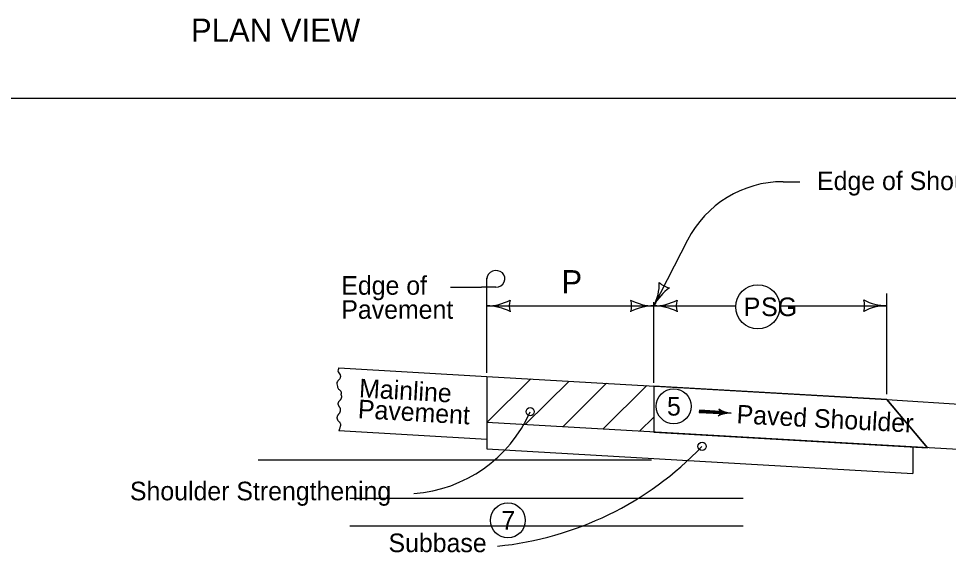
# Model space of a CAD drawing. Extents: x 6410 to 81668, y 3928 to 11667.
# Drawn here: x 7264 to 8064, y 8966 to 9425 of the extents above; entities that cross this region are included whole.
import ezdxf

# ---------------------------------------------------------------- set-up
doc = ezdxf.new("R2010")
doc.units = 0
for name, color, linetype in [('dsnCellElements', 7, 'Continuous'), ('dsnStdBlockModified', 7, 'Continuous'), ('dsnStdLabel', 7, 'Continuous'), ('dsnStdSection', 7, 'Continuous'), ('Level 11', 7, 'Continuous'), ('Level 14', 7, 'Continuous'), ('Level 3', 7, 'Continuous'), ('Level 7', 7, 'Continuous')]:
    doc.layers.add(name, color=color, linetype=linetype)

msp = doc.modelspace()

# ---------------------------------------------------------------- linework, layer by layer
at = {"layer": 'dsnStdBlockModified'}
for p, q in [((7539.49, 9124.58), (7666.95, 9117.17)), ((7666.95, 9117.17), (7666.95, 9063.16)), ((7666.95, 9117.17), (8011.25, 9097.15)), ((7810.72, 9108.8), (7810.72, 9069)), ((8010.79, 9097.34), (8010.79, 9097.34)), ((8011.25, 9097.23), (8146.01, 9088.85)), ((8011.25, 9097.15), (8046.29, 9055.7)), ((8243.06, 9044.35), (7666.95, 9077.58)), ((7539.52, 9070.57), (7666.95, 9063.16)), ((8033.48, 9070.85), (8033.48, 9070.85)), ((7666.95, 9063.16), (7666.95, 9054.74)), ((7666.95, 9054.74), (8033.48, 9033.6)), ((8033.48, 9056.43), (8033.48, 9033.6)), ((7470.23, 9045.23), (7808.74, 9045.23)), ((7548.9, 9012.25), (7887.4, 9012.25)), ((7548.9, 8988.58), (7887.4, 8988.58))]:
    msp.add_line(p, q, dxfattribs=at)
for points in [[(7539.49, 9124.58), (7538.99, 9120.98), (7540.03, 9119.47), (7540.89, 9117.18), (7540.29, 9115.12), (7538.38, 9112.74), (7537.86, 9110.84), (7538.38, 9108.54), (7539.25, 9106.17), (7540.29, 9105.45), (7541.67, 9102.92), (7541.66, 9102.08)], [(7539.7, 9084.97), (7539.91, 9085.22), (7540.11, 9085.48), (7540.46, 9086.04), (7540.74, 9086.63), (7540.86, 9086.93), (7540.96, 9087.25), (7541.09, 9087.87), (7541.14, 9088.49), (7541.1, 9089.08), (7541.04, 9089.35), (7541, 9089.49), (7540.95, 9089.62), (7540.74, 9090), (7540.46, 9090.36), (7540.16, 9090.73), (7539.91, 9091.12), (7539.77, 9091.41), (7539.63, 9091.69), (7539.37, 9092.26), (7539.17, 9092.83), (7539.1, 9093.12), (7539.04, 9093.42), (7539.03, 9093.55), (7539.03, 9093.67), (7539.18, 9094.45), (7539.39, 9094.97), (7539.65, 9095.48), (7540.1, 9096.12), (7540.61, 9096.66), (7541.13, 9097.21), (7541.36, 9097.51), (7541.56, 9097.86), (7541.77, 9098.33), (7541.92, 9098.8), (7542.02, 9099.28), (7542.06, 9099.52), (7542.07, 9099.64), (7542.08, 9099.76), (7542.03, 9100.26), (7541.88, 9100.78), (7541.83, 9100.91), (7541.77, 9101.03), (7541.73, 9101.16), (7541.7, 9101.29), (7541.66, 9102.08)], [(7539.7, 9084.97), (7539.49, 9084.73), (7539.24, 9084.5), (7539, 9084.26), (7538.82, 9083.99), (7538.68, 9083.7), (7538.54, 9083.42), (7538.28, 9082.85), (7538.17, 9082.56), (7538.08, 9082.28), (7538, 9081.98), (7537.98, 9081.84), (7537.96, 9081.69), (7537.97, 9081.17), (7538.1, 9080.66), (7538.3, 9080.14), (7538.56, 9079.63), (7539.01, 9078.99), (7539.52, 9078.45), (7540.04, 9077.9), (7540.27, 9077.6), (7540.47, 9077.26), (7540.87, 9076.31), (7540.98, 9075.83), (7540.99, 9075.36), (7540.95, 9075.07), (7540.91, 9074.78), (7540.85, 9074.49), (7540.78, 9074.21), (7540.47, 9073.06), (7540.29, 9072.45), (7540.09, 9071.85), (7539.87, 9071.26), (7539.74, 9070.97), (7539.6, 9070.68), (7539.52, 9070.57)]]:
    msp.add_spline(points, degree=3, dxfattribs=at)
at = {"layer": 'dsnStdLabel'}
msp.add_circle((7827.77, 9091.41), 15, dxfattribs=at)
at = {"layer": 'dsnStdSection'}
for p, q in [((7921.92, 9284.83), (7936.22, 9284.83)), ((7839.61, 9234.46), (7810.71, 9177.9)), ((7666.95, 9181.22), (7666.95, 9202.08)), ((7635.58, 9194.07), (7662.27, 9194.07)), ((7674.77, 9194.07), (7662.27, 9194.07)), ((8011.25, 9101.79), (8011.25, 9188.45)), ((7666.95, 9120.31), (7666.95, 9181.22)), ((7810.71, 9111.66), (7810.71, 9181.22)), ((7919.1, 9178.05), (8011.25, 9178.05)), ((7666.95, 9177.9), (7881.28, 9177.9)), ((7666.95, 9077.57), (7704.75, 9114.97)), ((7699.99, 9075.66), (7737.78, 9113.07)), ((7732.23, 9073.81), (7770.02, 9111.21)), ((7766.84, 9071.81), (7804.64, 9109.21)), ((7798.46, 9069.99), (7810.72, 9082.12)), ((7867.98, 9086.06), (7849.77, 9087.11)), ((7867.88, 9085.12), (7867.88, 9085.12)), ((7867.99, 9087.07), (7867.99, 9087.07))]:
    msp.add_line(p, q, dxfattribs=at)
for points in [[(7868.01, 9087), (7849.84, 9088.05), (7849.71, 9086.17), (7867.88, 9085.12), (7867.93, 9086.73), (7850.06, 9087.83), (7850, 9086.33), (7867.5, 9085.38), (7867.62, 9086.5), (7850.29, 9087.56), (7850.27, 9086.56), (7867.28, 9085.58), (7867.37, 9086.29), (7850.48, 9087.34), (7850.47, 9086.78), (7867.07, 9085.84)], [(7867.6, 9088.26), (7868.3, 9087.09), (7868.28, 9085.44), (7867.52, 9084.05), (7870.27, 9084.91), (7873.47, 9085.56), (7874.37, 9085.7), (7872.12, 9086.24), (7868.9, 9087.47), (7867.95, 9088.01), (7868.07, 9084.49), (7873.02, 9085.71), (7868.38, 9087.29), (7868.4, 9084.87), (7871.79, 9085.8), (7868.79, 9086.66), (7868.56, 9085.28), (7870.72, 9085.78), (7869.13, 9086.29), (7869, 9085.63), (7869.78, 9085.79)]]:
    msp.add_lwpolyline(points, dxfattribs=at)
msp.add_circle((7900.19, 9177.08), 18.93, dxfattribs=at)
for centre, radius, start, end in [((7921.92, 9192.4), 92.43, 90, 152.9341), ((7772.87, 9197.24), 42.5, 332.9341, 1.00659), ((7826.93, 9209.63), 16.42, 225.20075, 260.66745), ((7848.56, 9158.56), 42.5, 124.86161, 152.9341), ((7666.95, 9220.4), 42.5, 270, 298.07249), ((7702.59, 9177.9), 16.42, 162.26665, 197.73335), ((7775.08, 9177.9), 16.42, 342.26665, 17.73335), ((7810.71, 9220.4), 42.5, 241.92751, 270), ((7810.71, 9220.4), 42.5, 270, 298.07249), ((7846.35, 9177.9), 16.42, 162.26665, 197.73335), ((7975.62, 9178.05), 16.42, 342.26665, 17.73335), ((8011.25, 9220.55), 42.5, 241.92751, 270), ((8011.25, 9135.55), 42.5, 90, 118.07249), ((7666.95, 9135.4), 42.5, 61.92751, 90), ((7810.71, 9135.4), 42.5, 90, 118.07249), ((7810.71, 9135.4), 42.5, 61.92751, 90), ((7595.71, 9134.93), 118.88, 274.08506, 336.06992), ((7648.24, 9251.67), 282.03, 275.67842, 316.28441)]:
    msp.add_arc(centre, radius, start, end, dxfattribs=at)
for centre, major_axis, start_param, end_param in [((7674.77, 9201.2), (-7.81, 0), 1.570796, 6.283185), ((7864.21, 9086.28), (3.88, 0), 5.202895, 7.237436), ((7876.48, 9065.28), (22.17, 0), 1.537172, 2.061295), ((7879.27, 9105.7), (-22.17, 0), 0.954258, 1.478381)]:
    msp.add_ellipse(centre, major_axis=major_axis, ratio=0.913811, start_param=start_param, end_param=end_param, dxfattribs=at)
at = {"layer": 'Level 11'}
msp.add_line((8566.03, 9356.36), (6410.45, 9356.36), dxfattribs=at)
at = {"layer": 'Level 14'}
for centre in [(7704.26, 9086.76), (7704.26, 9086.76), (7852.2, 9056.91), (7852.2, 9056.91)]:
    msp.add_circle(centre, 3.54, dxfattribs=at)
at = {"layer": 'Level 3'}
for p, q in [((7810.76, 9108.81), (7810.72, 9069)), ((8011.25, 9097.23), (7810.76, 9108.81)), ((8046.29, 9055.7), (8011.25, 9097.23)), ((7810.72, 9069), (8046.29, 9055.7))]:
    msp.add_line(p, q, dxfattribs=at)
at = {"layer": 'Level 7'}
for centre in [(7827.77, 9091.41), (7685.06, 8993.21)]:
    msp.add_circle(centre, 15, dxfattribs=at)

# ---------------------------------------------------------------- texts
at = {"layer": 'dsnCellElements'}
msp.add_text('PLAN VIEW', height=20, dxfattribs=at).set_placement((7412.31, 9405.26))
msp.add_text('PLAN VIEW', height=20, dxfattribs=at).set_placement((7412.31, 9405.26))
at = {"layer": 'dsnStdSection'}
for s, height, p in [('Edge of Shoulder Strengthening', 16, (7951.12, 9277.59)), ('Edge of ', 16, (7541.7, 9187.48)), ('P', 20, (7731.12, 9188.64)), ('Pavement', 16, (7541.7, 9166.78)), ('P', 16, (7888.06, 9169.08)), ('SG', 16, (7902.98, 9169.08)), ('Shoulder Strengthening', 16, (7359.81, 9010.47)), ('Subbase', 16, (7582.32, 8965.83))]:
    msp.add_text(s, height=height, dxfattribs=at).set_placement(p)
for s, rotation, p in [('Mainline', 356.73462, (7556.71, 9099.24)), ('Pavement', 356.73462, (7555.69, 9081.27)), ('Paved Shoulder ', 356.98301, (7881.6, 9076.79))]:
    msp.add_text(s, height=16, rotation=rotation, dxfattribs=at).set_placement(p)
at = {"layer": 'Level 7'}
for s, p in [('5', (7822, 9083.41)), ('7', (7679.35, 8985.21))]:
    msp.add_text(s, height=16, dxfattribs=at).set_placement(p)

doc.saveas('drawing.dxf')
